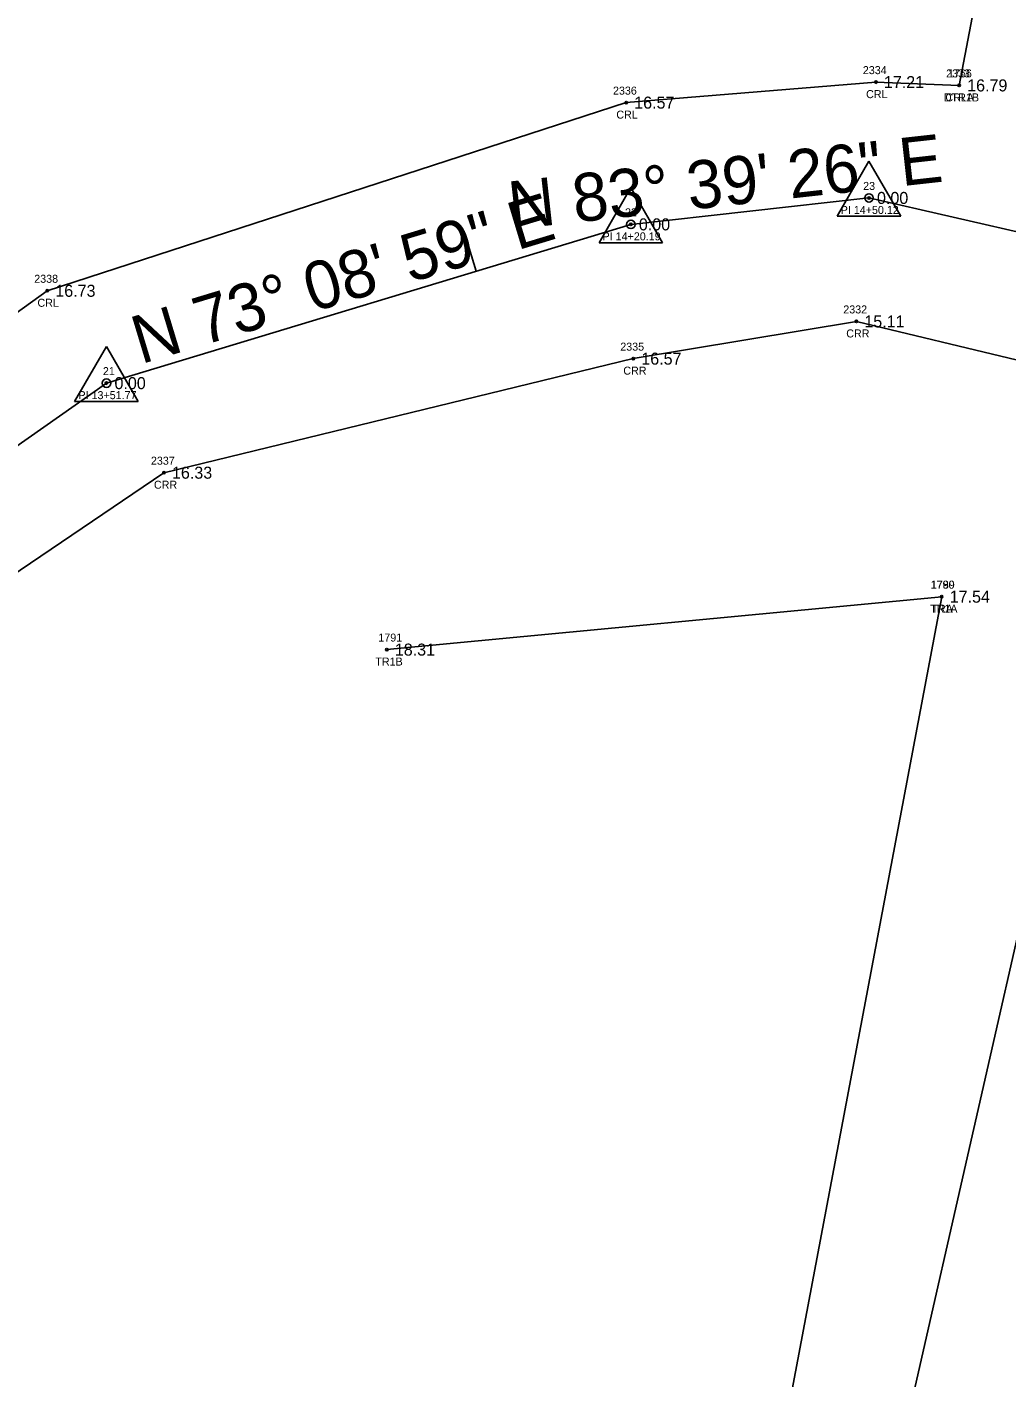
# Model space of a CAD drawing. Extents: x 2654414 to 2656963, y 761776 to 764965.
# Drawn here: x 2655563.1 to 2655685.5, y 763113.6 to 763282.4 of the extents above; entities that cross this region are included whole.
import ezdxf

# ---------------------------------------------------------------- set-up
doc = ezdxf.new("R2010")
doc.units = 0
for name, color, linetype in [('Default', 7, 'Continuous'), ('RD_EX_H2O', 7, 'Continuous'), ('RD_EX_H2O_txCode', 7, 'Continuous'), ('RD_EX_Road', 7, 'Continuous'), ('RD_EX_TX_H2O_ELEV', 7, 'Continuous'), ('RD_EX_TX_VEG_ELEV', 7, 'Continuous'), ('RD_EX_VEG', 7, 'Continuous'), ('RD_EX_VEG_txCode', 7, 'Continuous'), ('RD_HC_Cl', 7, 'Continuous'), ('RD_HC_Data', 7, 'Continuous'), ('RD_HC_Data_Tic', 7, 'Continuous'), ('RD_HC_Survey_ELEV', 7, 'Continuous'), ('RD_HC_txCode', 7, 'Continuous'), ('RD_SMD_Locator', 7, 'Continuous')]:
    doc.layers.add(name, color=color, linetype=linetype)

msp = doc.modelspace()

# ---------------------------------------------------------------- linework, layer by layer
at = {"layer": 'Default'}
for p, q in [((2655638.52, 763257.74), (2655668.26, 763261.04)), ((2655668.26, 763261.04), (2655813.77, 763227.81)), ((2655573.04, 763237.9), (2655638.52, 763257.74)), ((2655512.65, 763195.53), (2655573.04, 763237.9))]:
    msp.add_line(p, q, dxfattribs=at)
at = {"layer": 'RD_EX_H2O'}
for points in [[(2655761.66, 763536.79), (2655753.68, 763542.9), (2655743.24, 763538.2), (2655729.93, 763492.02), (2655706.75, 763396.29), (2655684.97, 763303.64), (2655679.52, 763275.1)], [(2655679.52, 763275.1), (2655669.12, 763275.51), (2655637.94, 763272.95), (2655565.65, 763249.44), (2655503.41, 763204.6), (2655446.32, 763155.55), (2655414.68, 763121.3), (2655403.66, 763111.5), (2655354.39, 763062.15), (2655287.73, 762993.08)], [(2655730.43, 763238.59), (2655686.81, 763240.78), (2655666.68, 763245.61), (2655638.83, 763240.96), (2655580.22, 763226.71), (2655520.12, 763186.01), (2655467.25, 763134.06), (2655436.95, 763097.37), (2655374.53, 763041.27), (2655306.29, 762970.79)]]:
    msp.add_lwpolyline(points, dxfattribs=at)
at = {"layer": 'RD_EX_Road'}
msp.add_lwpolyline([(2655700.99, 763232.28), (2655693.55, 763198.57), (2655671.65, 763102.04), (2655649.04, 763001.06), (2655627.27, 762906.23), (2655605, 762809.37), (2655598.99, 762783.09), (2655583.65, 762714.14), (2655561.97, 762618.32), (2655556.36, 762593.84), (2655548.11, 762557.14), (2655540.1, 762522.48), (2655518.03, 762425.04), (2655496.48, 762329.56), (2655475.55, 762236.62), (2655473.2, 762226.14), (2655466.57, 762197.5), (2655460.06, 762168.16), (2655454.26, 762143.78), (2655432.5, 762049.88), (2655410.7, 761955.51), (2655388.17, 761858.43), (2655373.5, 761793.95)], dxfattribs=at)
at = {"layer": 'RD_EX_VEG'}
msp.add_line((2655677.34, 763211.22), (2655608.05, 763204.61), dxfattribs=at)
msp.add_lwpolyline([(2655677.34, 763211.22), (2655657.55, 763106.21), (2655584.57, 762809.42), (2655537.65, 762768.62), (2655489.1, 762755.63)], dxfattribs=at)
at = {"layer": 'RD_HC_Cl'}
for p, q in [((2655638.52, 763257.74), (2655668.26, 763261.04)), ((2655668.26, 763261.04), (2655813.77, 763227.81)), ((2655573.04, 763237.9), (2655638.52, 763257.74)), ((2655512.65, 763195.53), (2655573.04, 763237.9))]:
    msp.add_line(p, q, dxfattribs=at)
at = {"layer": 'RD_HC_Data'}
for p, q in [((2655664.29, 763258.75), (2655668.26, 763265.63)), ((2655668.26, 763265.63), (2655672.23, 763258.75)), ((2655634.55, 763255.45), (2655638.52, 763262.33)), ((2655638.52, 763262.33), (2655642.49, 763255.45)), ((2655664.29, 763258.75), (2655672.23, 763258.75)), ((2655634.55, 763255.45), (2655642.49, 763255.45)), ((2655569.06, 763235.61), (2655573.04, 763242.49)), ((2655573.04, 763242.49), (2655577.01, 763235.61)), ((2655569.06, 763235.61), (2655577.01, 763235.61))]:
    msp.add_line(p, q, dxfattribs=at)
for centre in [(2655668.26, 763261.04), (2655638.52, 763257.74), (2655573.04, 763237.9)]:
    msp.add_circle(centre, 0.529, dxfattribs=at)
at = {"layer": 'RD_HC_Data_Tic'}
msp.add_line((2655619.2, 763251.89), (2655618.04, 763255.71), dxfattribs=at)
at = {"layer": 'RD_SMD_Locator'}
for centre in [(2655669.12, 763275.51), (2655679.52, 763275.1), (2655679.52, 763275.1), (2655637.94, 763272.95), (2655668.26, 763261.04), (2655638.52, 763257.74), (2655565.65, 763249.44), (2655666.68, 763245.61), (2655638.83, 763240.96), (2655573.04, 763237.9), (2655580.22, 763226.71), (2655677.34, 763211.22), (2655677.34, 763211.22), (2655608.05, 763204.61)]:
    msp.add_circle(centre, 0.15, dxfattribs=at)

# ---------------------------------------------------------------- texts
at = {"layer": 'RD_EX_H2O_txCode'}
for s, p in [('2334', (2655667.49, 763276.51)), ('2333', (2655677.89, 763276.1)), ('1766', (2655678.13, 763276.1)), ('2336', (2655636.29, 763273.95)), ('CRL', (2655667.9, 763273.51)), ('DTR1B', (2655677.62, 763273.1)), ('CRLA', (2655677.8, 763273.1)), ('CRL', (2655636.71, 763270.95)), ('2338', (2655564.02, 763250.44)), ('CRL', (2655564.42, 763247.44)), ('2332', (2655665.05, 763246.61)), ('CRR', (2655665.42, 763243.61)), ('2335', (2655637.2, 763241.96)), ('CRR', (2655637.58, 763238.96)), ('2337', (2655578.59, 763227.71)), ('CRR', (2655578.97, 763224.71))]:
    msp.add_text(s, height=1, dxfattribs=at).set_placement(p)
at = {"layer": 'RD_EX_TX_H2O_ELEV'}
for s, p in [('17.21', (2655670.12, 763274.76)), ('16.79', (2655680.52, 763274.35)), ('16.79', (2655680.52, 763274.35)), ('16.57', (2655638.94, 763272.2)), ('16.73', (2655566.65, 763248.69)), ('15.11', (2655667.68, 763244.86)), ('16.57', (2655639.83, 763240.21)), ('16.33', (2655581.22, 763225.96))]:
    msp.add_text(s, height=1.5, dxfattribs=at).set_placement(p)
at = {"layer": 'RD_EX_TX_VEG_ELEV'}
for s, p in [('17.54', (2655678.34, 763210.47)), ('17.54', (2655678.34, 763210.47)), ('18.31', (2655609.05, 763203.86))]:
    msp.add_text(s, height=1.5, dxfattribs=at).set_placement(p)
at = {"layer": 'RD_EX_VEG_txCode'}
for s, p in [('1790', (2655675.96, 763212.22)), ('1789', (2655675.99, 763212.22)), ('TR1A', (2655675.89, 763209.22)), ('TRA', (2655676.06, 763209.22)), ('1791', (2655606.99, 763205.61)), ('TR1B', (2655606.62, 763202.61))]:
    msp.add_text(s, height=1, dxfattribs=at).set_placement(p)
at = {"layer": 'RD_HC_Data'}
for s, rotation, p in [('N 83%%d 39\' 26" E', 6.3429, (2655623.58, 763257.08)), ('N 73%%d 08\' 59" E', 16.8503, (2655577.34, 763240.25))]:
    msp.add_text(s, height=6, rotation=rotation, dxfattribs=at).set_placement(p)
at = {"layer": 'RD_HC_Survey_ELEV'}
for p in [(2655669.26, 763260.29), (2655639.52, 763256.99), (2655574.04, 763237.15)]:
    msp.add_text('0.00', height=1.5, dxfattribs=at).set_placement(p)
at = {"layer": 'RD_HC_txCode'}
for s, p in [('23', (2655667.53, 763262.04)), ('22', (2655637.79, 763258.74)), ('PI 14+50.12', (2655664.73, 763259.04)), ('PI 14+20.19', (2655634.99, 763255.74)), ('21', (2655572.59, 763238.9)), ('PI 13+51.77', (2655569.54, 763235.9))]:
    msp.add_text(s, height=1, dxfattribs=at).set_placement(p)

doc.saveas('drawing.dxf')
